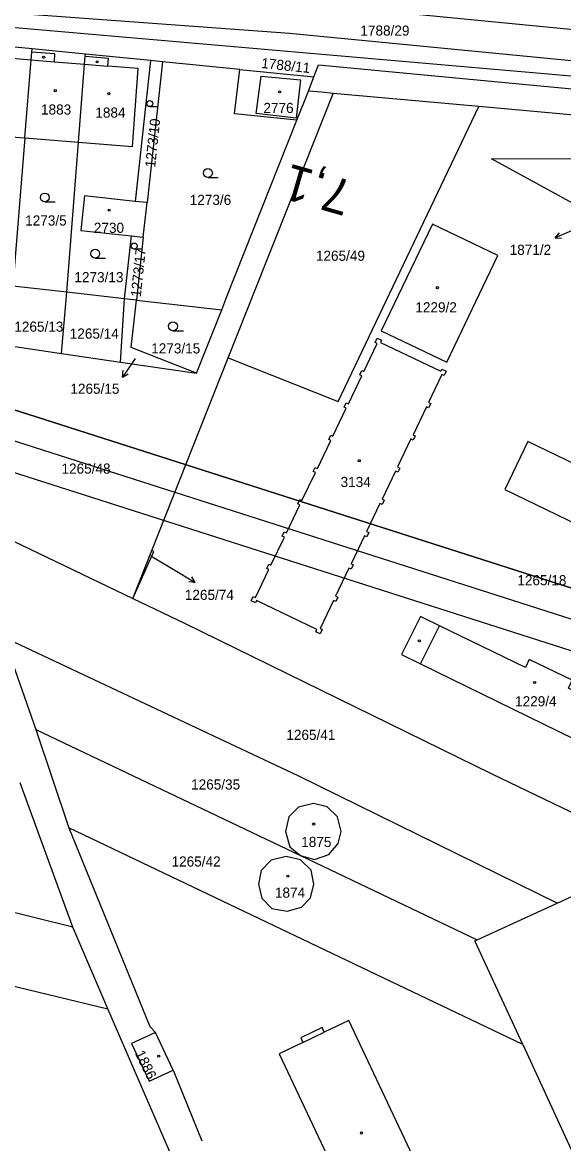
# Model space of a CAD drawing. Extents: x -779330 to -774454, y -1144748 to -1142831.
# Drawn here: x -777260.7 to -777170.1, y -1144037.5 to -1143849.7 of the extents above; entities that cross this region are included whole.
import ezdxf

# ---------------------------------------------------------------- set-up
doc = ezdxf.new("R2010")
doc.units = 0
for name, color, linetype in [('Hranice parcel', 7, 'Continuous'), ('Parcelní čísla', 7, 'Continuous'), ('Pop  PČ popisy', 7, 'Continuous'), ('Vnitřní kresba', 7, 'Continuous'), ('Vrstva 1', 7, 'Continuous'), ('Vrstva 7', 7, 'Continuous'), ('Značky budov', 7, 'Continuous'), ('Značky kultur', 7, 'Continuous')]:
    doc.layers.add(name, color=color, linetype=linetype)

msp = doc.modelspace()

# ---------------------------------------------------------------- linework, layer by layer
at = {"layer": 'Hranice parcel'}
for p, q in [((-777259.1, -1143854.15), (-777268.04, -1143853.26)), ((-777250.16, -1143855.03), (-777259.1, -1143854.15)), ((-777250.19, -1143855.41), (-777250.16, -1143855.03)), ((-777239.27, -1143856.11), (-777250.16, -1143855.03)), ((-777239.27, -1143856.11), (-777241.85, -1143879.69)), ((-777237.27, -1143856.31), (-777239.86, -1143879.9)), ((-777237.27, -1143856.31), (-777239.27, -1143856.11)), ((-777224.33, -1143857.6), (-777237.27, -1143856.31)), ((-777224.33, -1143857.6), (-777211.92, -1143858.84)), ((-777212.82, -1143861.22), (-777211.92, -1143858.84)), ((-777226.25, -1143905.92), (-777208.67, -1143861.6)), ((-777214.78, -1143866.06), (-777212.82, -1143861.22)), ((-777210.66, -1143861.42), (-777212.82, -1143861.22)), ((-777208.67, -1143861.6), (-777210.66, -1143861.42)), ((-777184.32, -1143863.79), (-777208.67, -1143861.6)), ((-777125.43, -1143869.09), (-777184.32, -1143863.79)), ((-777269.3, -1143868.34), (-777260.32, -1143869.06)), ((-777260.32, -1143869.06), (-777262.35, -1143893.9)), ((-777260.32, -1143869.06), (-777251.32, -1143869.77)), ((-777253.28, -1143894.92), (-777251.32, -1143869.77)), ((-777239.86, -1143879.9), (-777241.85, -1143879.69)), ((-777240.49, -1143885.7), (-777239.86, -1143879.9)), ((-777243.63, -1143896.02), (-777242.48, -1143885.49)), ((-777242.48, -1143885.49), (-777240.49, -1143885.7)), ((-777240.49, -1143885.7), (-777241.64, -1143896.24)), ((-777253.28, -1143894.92), (-777262.35, -1143893.9)), ((-777254.2, -1143905.16), (-777253.28, -1143894.92)), ((-777243.63, -1143896.02), (-777253.28, -1143894.92)), ((-777244.31, -1143906.62), (-777243.63, -1143896.02)), ((-777241.64, -1143896.24), (-777243.63, -1143896.02)), ((-777241.64, -1143896.24), (-777227.36, -1143897.85)), ((-777231.58, -1143908.5), (-777227.36, -1143897.85)), ((-777263.1, -1143903.84), (-777254.2, -1143905.16)), ((-777254.2, -1143905.16), (-777244.31, -1143906.62)), ((-777239.05, -1143938.18), (-777226.25, -1143905.92)), ((-777244.31, -1143906.62), (-777231.58, -1143908.5)), ((-777262.34, -1143936.58), (-777242.24, -1143946.21)), ((-777242.24, -1143946.21), (-777239.05, -1143938.18)), ((-777263.88, -1143952.69), (-777258.48, -1143968.19)), ((-777258.48, -1143968.19), (-777252.93, -1143984.66)), ((-777252.26, -1144001.3), (-777261.12, -1143977.11)), ((-777176.95, -1144020.96), (-777252.93, -1143984.66)), ((-777252.26, -1144001.3), (-777295.44, -1143990.58)), ((-777184.6, -1144003.38), (-777171.18, -1143997.24)), ((-777301.08, -1144001.76), (-777246.41, -1144014.94)), ((-777246.41, -1144014.94), (-777252.26, -1144001.3)), ((-777229.85, -1144053.13), (-777246.41, -1144014.94)), ((-777235.49, -1144025.23), (-777238.44, -1144018.91)), ((-777235.49, -1144025.23), (-777230.69, -1144037.07))]:
    msp.add_line(p, q, dxfattribs=at)
for points in [[(-777313.47, -1143830.96), (-777307.07, -1143834.06), (-777294.79, -1143837.91), (-777291.06, -1143838.91), (-777215.44, -1143846.33), (-777156.34, -1143852.08), (-777155.61, -1143848.73), (-777137.5, -1143850.27)], [(-776998.39, -1143882.22), (-777014.02, -1143874.66), (-777035.36, -1143870.54), (-777167.58, -1143858.82), (-777281.88, -1143848.9), (-777289.53, -1143848.43), (-777292.27, -1143847.75), (-777303.16, -1143845.03)], [(-777260.32, -1143869.06), (-777259.25, -1143855.97), (-777259.14, -1143854.68), (-777259.1, -1143854.15)], [(-777251.32, -1143869.77), (-777242.31, -1143870.49), (-777241.35, -1143857.44), (-777246.42, -1143857.02), (-777246.31, -1143855.73), (-777250.19, -1143855.41)], [(-777251.32, -1143869.77), (-777250.3, -1143856.7), (-777250.19, -1143855.41)], [(-777211.92, -1143858.84), (-777211.13, -1143856.84), (-777167.5, -1143860.96), (-777150.77, -1143862.48), (-777035.76, -1143872.38), (-777017.82, -1143877.1)], [(-777214.78, -1143866.06), (-777225.23, -1143865.01), (-777224.33, -1143857.6)], [(-777226.25, -1143905.92), (-777207.85, -1143913.23), (-777184.32, -1143863.79)], [(-777227.36, -1143897.85), (-777226.49, -1143895.64), (-777214.78, -1143866.06)], [(-777166.67, -1143881.06), (-777182.17, -1143872.56), (-777151.21, -1143872.43)], [(-777241.85, -1143879.69), (-777250.33, -1143878.76), (-777250.96, -1143884.56), (-777242.48, -1143885.49)], [(-777192.05, -1143883.51), (-777200.68, -1143901.4), (-777189.65, -1143906.65), (-777181.11, -1143888.77), (-777192.05, -1143883.51)], [(-777231.58, -1143908.5), (-777242.51, -1143904.19), (-777241.64, -1143896.24)], [(-777195.31, -1143918.78), (-777194.95, -1143918.95), (-777195.3, -1143919.68), (-777195.66, -1143919.5), (-777197.91, -1143924.19), (-777197.55, -1143924.36), (-777197.89, -1143925.08), (-777198.25, -1143924.91), (-777200.5, -1143929.6), (-777200.14, -1143929.77), (-777200.49, -1143930.49), (-777200.85, -1143930.32), (-777203.1, -1143935.01), (-777202.74, -1143935.18), (-777203.08, -1143935.9), (-777203.44, -1143935.73), (-777205.69, -1143940.42), (-777205.33, -1143940.59), (-777205.68, -1143941.31), (-777206.04, -1143941.14), (-777208.29, -1143945.83), (-777207.93, -1143946), (-777208.27, -1143946.72), (-777208.63, -1143946.55), (-777210.88, -1143951.24), (-777210.52, -1143951.41), (-777210.87, -1143952.13), (-777211.59, -1143951.78), (-777211.42, -1143951.42), (-777221.51, -1143946.58), (-777221.68, -1143946.94), (-777222.4, -1143946.6), (-777222.06, -1143945.88), (-777221.7, -1143946.05), (-777219.45, -1143941.36), (-777219.81, -1143941.19), (-777219.46, -1143940.47), (-777219.1, -1143940.64), (-777216.86, -1143935.96), (-777217.22, -1143935.78), (-777216.87, -1143935.06), (-777216.51, -1143935.24), (-777214.26, -1143930.55), (-777214.62, -1143930.38), (-777214.28, -1143929.66), (-777213.92, -1143929.83), (-777211.67, -1143925.14), (-777212.03, -1143924.97), (-777211.69, -1143924.25), (-777211.33, -1143924.42), (-777209.08, -1143919.74), (-777209.44, -1143919.56), (-777209.09, -1143918.84), (-777208.73, -1143919.02), (-777206.49, -1143914.33), (-777206.85, -1143914.16), (-777206.5, -1143913.44), (-777206.14, -1143913.61), (-777203.89, -1143908.92), (-777204.25, -1143908.75), (-777203.91, -1143908.03), (-777203.55, -1143908.2), (-777201.3, -1143903.52), (-777201.66, -1143903.34), (-777201.32, -1143902.62), (-777200.6, -1143902.97), (-777200.77, -1143903.33), (-777190.66, -1143908.15), (-777190.49, -1143907.79), (-777189.76, -1143908.14), (-777190.11, -1143908.86), (-777190.47, -1143908.68), (-777192.72, -1143913.37), (-777192.36, -1143913.55), (-777192.7, -1143914.27), (-777193.07, -1143914.09), (-777195.31, -1143918.78)], [(-777153.45, -1143930.87), (-777176.1, -1143919.92), (-777179.97, -1143927.94), (-777157.35, -1143938.91), (-777156.78, -1143937.74), (-777151.69, -1143940.24), (-777148.31, -1143933.36), (-777153.45, -1143930.87)], [(-777242.24, -1143946.21), (-777238.7, -1143938.36), (-777239.05, -1143938.18)], [(-777242.24, -1143946.21), (-777233.61, -1143950.34), (-777182.11, -1143975.59), (-777151.49, -1143990.35)], [(-777176.5, -1143957.76), (-777190.89, -1143950.8), (-777194.08, -1143949.25), (-777197.24, -1143955.62), (-777194.04, -1143957.18), (-777157.99, -1143974.82), (-777154.93, -1143968.2), (-777169.31, -1143961.24), (-777168.67, -1143959.91), (-777175.86, -1143956.43), (-777176.5, -1143957.76)], [(-777171.18, -1143997.24), (-777214.44, -1143976.01), (-777263.88, -1143952.69)], [(-777258.48, -1143968.19), (-777214.18, -1143989.29), (-777184.6, -1144003.38)], [(-777211.83, -1143989.97), (-777209.4, -1143989.12), (-777207.86, -1143987.26), (-777207.36, -1143985.24), (-777207.97, -1143982.81), (-777209.69, -1143981.14), (-777212.01, -1143980.59), (-777214.5, -1143981.16), (-777216.09, -1143982.78), (-777216.66, -1143985.24), (-777215.92, -1143987.82), (-777214.18, -1143989.29), (-777211.83, -1143989.97)], [(-777252.93, -1143984.66), (-777239.41, -1144017.93), (-777238.44, -1144018.91)], [(-777221.22, -1143994.09), (-777220.62, -1143996.4), (-777218.96, -1143998.16), (-777216.39, -1143998.63), (-777214.02, -1143997.96), (-777212.48, -1143996.38), (-777211.92, -1143994.09), (-777212.38, -1143991.73), (-777214.14, -1143989.99), (-777216.57, -1143989.44), (-777219.09, -1143990.07), (-777220.72, -1143991.8), (-777221.22, -1143994.09)], [(-777171.18, -1143997.24), (-777168.61, -1143996.07), (-777167.13, -1143999.23)], [(-777176.95, -1144020.96), (-777184.99, -1144003.56), (-777184.6, -1144003.38)], [(-777187.43, -1144056.45), (-777206.08, -1144016.93), (-777210.19, -1144018.89), (-777210.56, -1144018.11), (-777214.13, -1144019.82), (-777213.76, -1144020.59), (-777217.75, -1144022.5), (-777205.57, -1144048.32)], [(-777238.44, -1144018.91), (-777242.48, -1144020.79), (-777239.52, -1144027.11), (-777235.49, -1144025.23)], [(-777176.95, -1144020.96), (-777163.68, -1144049.68), (-777147.08, -1144042), (-777151.17, -1144033.27)]]:
    msp.add_lwpolyline(points, dxfattribs=at)
at = {"layer": 'Pop  PČ popisy'}
for p, q in [((-777168.78, -1143884.63), (-777171.54, -1143885.8)), ((-777171.54, -1143885.8), (-777170.82, -1143884.95)), ((-777171.54, -1143885.8), (-777170.43, -1143885.87)), ((-777241.83, -1143906.04), (-777242.27, -1143906.66)), ((-777242.27, -1143906.66), (-777243.99, -1143909.12)), ((-777243.99, -1143909.12), (-777243.83, -1143908.01)), ((-777243.99, -1143909.12), (-777243.01, -1143908.58)), ((-777239.2, -1143939.1), (-777234.34, -1143941.99)), ((-777234.34, -1143941.99), (-777231.77, -1143943.54)), ((-777231.77, -1143943.54), (-777232.88, -1143943.45)), ((-777231.77, -1143943.54), (-777232.37, -1143942.59))]:
    msp.add_line(p, q, dxfattribs=at)
at = {"layer": 'Vnitřní kresba'}
for p, q in [((-777216.02, -1143851.57), (-777281.53, -1143846.8)), ((-777166.52, -1143856.36), (-777216.02, -1143851.57)), ((-777255.27, -1143855), (-777259.14, -1143854.68)), ((-777255.37, -1143856.29), (-777255.27, -1143855)), ((-777264.32, -1143855.56), (-777259.25, -1143855.97)), ((-777259.25, -1143855.97), (-777255.37, -1143856.29)), ((-777255.37, -1143856.29), (-777250.3, -1143856.7)), ((-777250.3, -1143856.7), (-777246.42, -1143857.02)), ((-777221.57, -1143864.99), (-777220.76, -1143858.72)), ((-777220.76, -1143858.72), (-777214.17, -1143859.35)), ((-777214.17, -1143859.35), (-777214.9, -1143865.74)), ((-777214.9, -1143865.74), (-777221.57, -1143864.99)), ((-777194.04, -1143957.18), (-777190.89, -1143950.8)), ((-777213.76, -1144020.59), (-777210.19, -1144018.89))]:
    msp.add_line(p, q, dxfattribs=at)
at = {"layer": 'Vrstva 1'}
for points in [[(-776606.88, -1143822.95), (-777806.9, -1143438.86), (-777897.43, -1143721.71), (-776697.42, -1144105.81)], [(-776700.65, -1144099.52), (-777891.15, -1143718.47), (-777803.66, -1143445.14), (-776613.17, -1143826.19)], [(-776619.45, -1143829.42), (-777605.19, -1143513.91), (-777689.63, -1143777.73), (-776703.89, -1144093.24)], [(-776703.89, -1144093.24), (-777689.63, -1143777.73), (-777605.19, -1143513.91), (-776619.45, -1143829.42)]]:
    msp.add_lwpolyline(points, close=True, dxfattribs=at)
at = {"layer": 'Značky budov'}
for centre in [(-777257.17, -1143855.55), (-777248.21, -1143856.3), (-777255.22, -1143861.14), (-777246.25, -1143861.65), (-777217.66, -1143861.34), (-777246.19, -1143881.15), (-777191.24, -1143894.15), (-777204.32, -1143923.14), (-777194.26, -1143953.31), (-777174.96, -1143960.29), (-777211.96, -1143984.01), (-777216.29, -1143992.74), (-777237.9, -1144022.88), (-777203.96, -1144035.77)]:
    msp.add_circle(centre, 0.175, dxfattribs=at)
at = {"layer": 'Značky kultur'}
for p, q in [((-777239.39, -1143863.81), (-777238.21, -1143863.81)), ((-777229.67, -1143875.69), (-777227.92, -1143875.69)), ((-777256.97, -1143879.79), (-777255.22, -1143879.79)), ((-777248.54, -1143889.21), (-777246.79, -1143889.21)), ((-777241.99, -1143887.67), (-777240.82, -1143887.67)), ((-777235.52, -1143901.37), (-777233.77, -1143901.37))]:
    msp.add_line(p, q, dxfattribs=at)
for centre, radius in [((-777239.39, -1143863.31), 0.502), ((-777229.67, -1143874.94), 0.75), ((-777256.97, -1143879.04), 0.75), ((-777242, -1143887.17), 0.502), ((-777248.54, -1143888.46), 0.75), ((-777235.52, -1143900.62), 0.75)]:
    msp.add_circle(centre, radius, dxfattribs=at)

# ---------------------------------------------------------------- texts
at = {"layer": 'Parcelní čísla'}
for s, p in [('1788/29', (-777204.13, -1143851.93)), ('1883', (-777257.61, -1143865.15)), ('1884', (-777248.51, -1143865.67)), ('2776', (-777220.37, -1143864.89)), ('1273/6', (-777232.71, -1143880.29)), ('1273/5', (-777260.26, -1143883.74)), ('2730', (-777248.76, -1143884.97)), ('1871/2', (-777179.14, -1143888.65)), ('1265/49', (-777211.58, -1143889.65)), ('1273/13', (-777252.02, -1143893.24)), ('1229/2', (-777194.93, -1143898.29)), ('1265/13', (-777262.08, -1143901.53)), ('1265/14', (-777252.8, -1143902.69)), ('1273/15', (-777239.16, -1143905.17)), ('1265/15', (-777252.69, -1143911.93)), ('1265/48', (-777254.18, -1143925.31)), ('3134', (-777207.45, -1143927.55)), ('1265/18', (-777177.85, -1143944.01)), ('1265/74', (-777233.53, -1143946.46)), ('1229/4', (-777178.23, -1143964.29)), ('1265/41', (-777216.53, -1143969.91)), ('1265/35', (-777232.48, -1143978.23)), ('1875', (-777214.04, -1143987.86)), ('1265/42', (-777235.75, -1143991.13)), ('1874', (-777218.44, -1143996.35))]:
    msp.add_text(s, height=1.7, dxfattribs=at).set_placement(p)
for s, rotation, p in [('1788/11', 354, (-777220.79, -1143857.34)), ('1273/10', 84, (-777238.5, -1143874.09)), ('1273/17', 84, (-777240.91, -1143895.78)), ('1886', 296, (-777241.93, -1144022.42))]:
    msp.add_text(s, height=1.7, rotation=rotation, dxfattribs=at).set_placement(p)
at = {"layer": 'Vrstva 7'}
msp.add_text('7,1', height=6, rotation=163.9802, dxfattribs=at).set_placement((-777205.13, -1143876.43))

doc.saveas('drawing.dxf')
